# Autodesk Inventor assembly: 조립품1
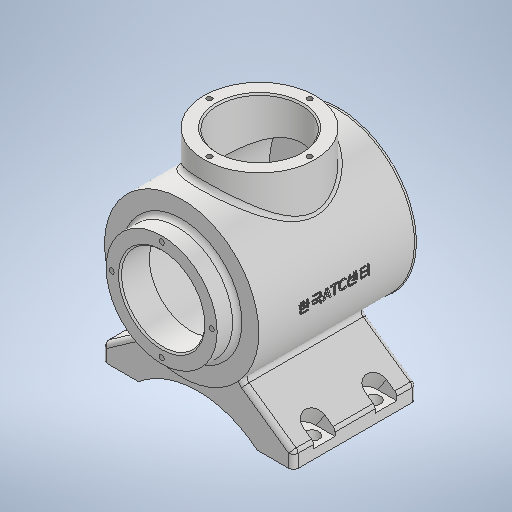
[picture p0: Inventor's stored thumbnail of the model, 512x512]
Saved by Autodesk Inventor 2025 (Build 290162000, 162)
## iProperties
Created: 2024-07
Part Number: 조립품1
Document SubType Name: Assembly
Designer: 학생
Author: 학생
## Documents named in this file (2)
- C:\Users\학생\Desktop\새 폴더\조립품1.iam
- C:\Users\학생\Desktop\새 폴더\부품1.ipt
